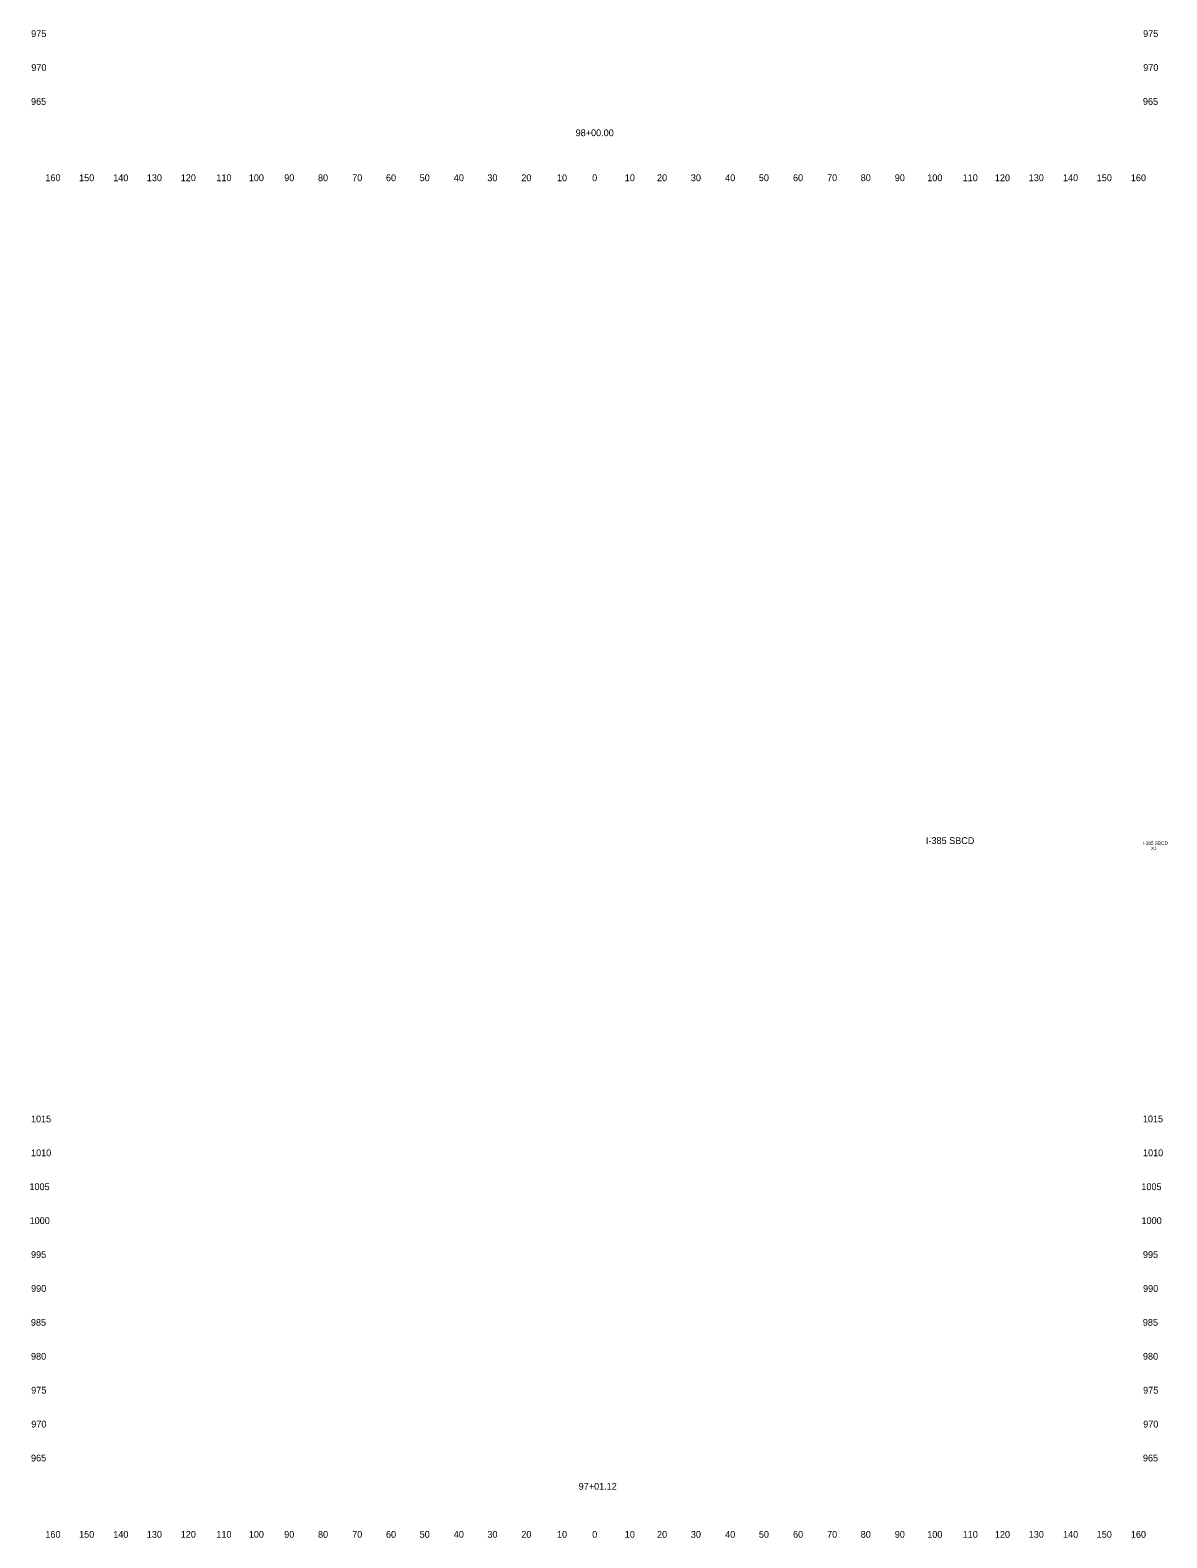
# Model space of a CAD drawing. Extents: x 4994 to 6876, y 4997 to 8804.
# Drawn here: x 4993.6 to 5328.7, y 4997.5 to 5442 of the extents above; entities that cross this region are included whole.
import ezdxf

# ---------------------------------------------------------------- set-up
doc = ezdxf.new("R2010")
doc.units = 0
for name, color, linetype in [('RD_SHT_ID', 7, 'Continuous'), ('RD_XS_TX_Offset', 7, 'Continuous'), ('RD_XS_TX_Station', 7, 'Continuous')]:
    doc.layers.add(name, color=color, linetype=linetype)

msp = doc.modelspace()

# ---------------------------------------------------------------- texts
at = {"layer": 'RD_SHT_ID'}
for s, height, p in [('I-385 SBCD', 2, (5257.69, 5202.06)), ('I-385 SBCD', 1, (5321.63, 5201.8)), ('X1', 1, (5324.02, 5200.3))]:
    msp.add_text(s, height=height, dxfattribs=at).set_placement(p)
at = {"layer": 'RD_XS_TX_Offset'}
for s, p in [('975', (4993.91, 5440)), ('975', (5321.71, 5440)), ('970', (4993.94, 5430)), ('970', (5321.74, 5430)), ('965', (4993.86, 5420)), ('965', (5321.66, 5420)), ('160', (4998.1, 5397.5)), ('150', (5008.04, 5397.5)), ('140', (5018.1, 5397.5)), ('130', (5027.99, 5397.5)), ('120', (5038.01, 5397.5)), ('110', (5048.51, 5397.5)), ('100', (5058.07, 5397.5)), ('90', (5068.5, 5397.5)), ('80', (5078.46, 5397.5)), ('70', (5088.54, 5397.5)), ('60', (5098.5, 5397.5)), ('50', (5108.43, 5397.5)), ('40', (5118.5, 5397.5)), ('30', (5128.39, 5397.5)), ('20', (5138.4, 5397.5)), ('10', (5148.91, 5397.5)), ('0', (5159.3, 5397.5)), ('0', (5159.3, 5397.5)), ('10', (5168.91, 5397.5)), ('20', (5178.4, 5397.5)), ('30', (5188.39, 5397.5)), ('40', (5198.5, 5397.5)), ('50', (5208.43, 5397.5)), ('60', (5218.5, 5397.5)), ('70', (5228.54, 5397.5)), ('80', (5238.46, 5397.5)), ('90', (5248.5, 5397.5)), ('100', (5258.07, 5397.5)), ('110', (5268.51, 5397.5)), ('120', (5278.01, 5397.5)), ('130', (5287.99, 5397.5)), ('140', (5298.1, 5397.5)), ('150', (5308.04, 5397.5)), ('160', (5318.1, 5397.5)), ('1015', (4993.85, 5120)), ('1015', (5321.65, 5120)), ('1010', (4993.88, 5110)), ('1010', (5321.68, 5110)), ('1005', (4993.4, 5100)), ('1005', (5321.2, 5100)), ('1000', (4993.44, 5090)), ('1000', (5321.24, 5090)), ('995', (4993.86, 5080)), ('995', (5321.66, 5080)), ('990', (4993.89, 5070)), ('990', (5321.69, 5070)), ('985', (4993.83, 5060)), ('985', (5321.63, 5060)), ('980', (4993.86, 5050)), ('980', (5321.66, 5050)), ('975', (4993.91, 5040)), ('975', (5321.71, 5040)), ('970', (4993.94, 5030)), ('970', (5321.74, 5030)), ('965', (4993.86, 5020)), ('965', (5321.66, 5020)), ('160', (4998.1, 4997.5)), ('150', (5008.04, 4997.5)), ('140', (5018.1, 4997.5)), ('130', (5027.99, 4997.5)), ('120', (5038.01, 4997.5)), ('110', (5048.51, 4997.5)), ('100', (5058.07, 4997.5)), ('90', (5068.5, 4997.5)), ('80', (5078.46, 4997.5)), ('70', (5088.54, 4997.5)), ('60', (5098.5, 4997.5)), ('50', (5108.43, 4997.5)), ('40', (5118.5, 4997.5)), ('30', (5128.39, 4997.5)), ('20', (5138.4, 4997.5)), ('10', (5148.91, 4997.5)), ('0', (5159.3, 4997.5)), ('0', (5159.3, 4997.5)), ('10', (5168.91, 4997.5)), ('20', (5178.4, 4997.5)), ('30', (5188.39, 4997.5)), ('40', (5198.5, 4997.5)), ('50', (5208.43, 4997.5)), ('60', (5218.5, 4997.5)), ('70', (5228.54, 4997.5)), ('80', (5238.46, 4997.5)), ('90', (5248.5, 4997.5)), ('100', (5258.07, 4997.5)), ('110', (5268.51, 4997.5)), ('120', (5278.01, 4997.5)), ('130', (5287.99, 4997.5)), ('140', (5298.1, 4997.5)), ('150', (5308.04, 4997.5)), ('160', (5318.1, 4997.5))]:
    msp.add_text(s, height=2, dxfattribs=at).set_placement(p)
at = {"layer": 'RD_XS_TX_Station'}
for s, p in [('98+00.00', (5154.42, 5410.77)), ('97+01.12', (5155.31, 5011.66))]:
    msp.add_text(s, height=2, dxfattribs=at).set_placement(p)

doc.saveas('drawing.dxf')
